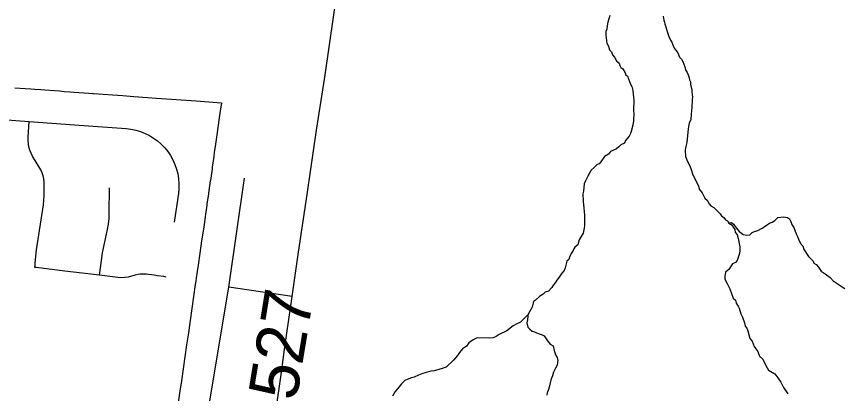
# Model space of a CAD drawing. Extents: x 0 to 39.3, y -3.9 to 22.
# Drawn here: x 5.137 to 6.099, y 18.028 to 18.467 of the extents above; entities that cross this region are included whole.
import ezdxf

# ---------------------------------------------------------------- set-up
doc = ezdxf.new("R2010")
doc.units = 0
for name, color, linetype in [('GM_X_Corporation', 7, 'Continuous'), ('GM_X_Minor_River', 7, 'Continuous'), ('GM_X_State_Route', 7, 'Continuous'), ('GM_X_Township_Road', 7, 'Continuous'), ('GM_X_Township_Road_Text', 7, 'Continuous')]:
    doc.layers.add(name, color=color, linetype=linetype)

msp = doc.modelspace()

# ---------------------------------------------------------------- linework, layer by layer
at = {"layer": 'GM_X_Corporation'}
msp.add_lwpolyline([(5.13496, 18.38436), (5.14692, 18.38347), (5.15336, 18.38299), (5.15826, 18.38263), (5.16517, 18.38212), (5.16959, 18.3818), (5.18092, 18.38096), (5.18693, 18.38052), (5.19225, 18.38012), (5.19923, 18.37961), (5.20359, 18.37928), (5.21492, 18.37846), (5.22098, 18.37801), (5.22526, 18.3777), (5.22625, 18.37763), (5.23759, 18.3768), (5.24892, 18.37597), (5.26025, 18.37515), (5.27336, 18.37419), (5.28901, 18.37305), (5.2995, 18.37228), (5.34556, 18.36892), (5.37507, 18.36676), (5.37501, 18.36637), (5.37372, 18.35735), (5.3722, 18.34667), (5.37012, 18.33214), (5.36817, 18.31847), (5.36678, 18.30877), (5.36615, 18.30432), (5.36439, 18.29203), (5.36411, 18.29009), (5.36214, 18.2763), (5.36211, 18.27607), (5.36006, 18.26176), (5.35996, 18.261), (5.35819, 18.24861), (5.35805, 18.24766), (5.35651, 18.23689), (5.35613, 18.23425), (5.35604, 18.23361), (5.35484, 18.22518), (5.35404, 18.21986), (5.35197, 18.20598), (5.3499, 18.1916), (5.34793, 18.17788), (5.3458, 18.1631), (5.34526, 18.15935), (5.34469, 18.15537), (5.34469, 18.15536), (5.34269, 18.14145), (5.34068, 18.12744), (5.33864, 18.11329), (5.33658, 18.09894), (5.33459, 18.08507), (5.33257, 18.07101), (5.33256, 18.071), (5.33057, 18.0571), (5.33057, 18.0571), (5.32853, 18.04296), (5.32648, 18.02866), (5.32442, 18.01434)], dxfattribs=at)
at = {"layer": 'GM_X_Minor_River'}
for points in [[(5.82631, 18.46825), (5.82428, 18.46068), (5.82345, 18.45651), (5.823, 18.45233), (5.82181, 18.44969), (5.82174, 18.44512), (5.82208, 18.44284), (5.82277, 18.43864), (5.82311, 18.43635), (5.82494, 18.43252), (5.82601, 18.42832), (5.82826, 18.42599), (5.82972, 18.42254), (5.83196, 18.41984), (5.83417, 18.41562), (5.83716, 18.4129), (5.83826, 18.41022), (5.83936, 18.40792), (5.84161, 18.40636), (5.8442, 18.40175), (5.84492, 18.39945), (5.84717, 18.39789), (5.84934, 18.39139), (5.85043, 18.38833), (5.85191, 18.38564), (5.85335, 18.38105), (5.85366, 18.37686), (5.85398, 18.37343), (5.85431, 18.37038), (5.85409, 18.35745), (5.85442, 18.3544), (5.85438, 18.35174), (5.85395, 18.34909), (5.8539, 18.34566), (5.85305, 18.34073), (5.85141, 18.33354), (5.85061, 18.33089), (5.84904, 18.32787), (5.84477, 18.323), (5.84357, 18.3196), (5.83936, 18.31777), (5.83666, 18.31516), (5.83434, 18.3133), (5.83012, 18.31109), (5.82744, 18.30999), (5.82511, 18.30699), (5.82013, 18.30442), (5.81584, 18.29803), (5.8139, 18.29578), (5.81161, 18.29506), (5.80812, 18.29132), (5.80465, 18.28833), (5.80308, 18.2857), (5.80073, 18.28156), (5.79836, 18.27589), (5.79678, 18.2725), (5.79587, 18.26376), (5.79506, 18.26074), (5.79502, 18.25845), (5.79534, 18.25464), (5.79567, 18.2516), (5.796, 18.24854), (5.79693, 18.23598), (5.79718, 18.22875), (5.7971, 18.2238), (5.79667, 18.22077), (5.79543, 18.21508), (5.79074, 18.20718), (5.78912, 18.2015), (5.78566, 18.1989), (5.78448, 18.19664), (5.78329, 18.194), (5.78135, 18.19137), (5.77976, 18.18721), (5.77895, 18.18456), (5.77663, 18.18232), (5.7746, 18.17475), (5.77341, 18.17173), (5.77069, 18.16835), (5.76758, 18.16384), (5.76486, 18.16047), (5.7629, 18.15708), (5.76096, 18.15483), (5.75901, 18.15182), (5.75514, 18.1477), (5.75132, 18.14625), (5.749, 18.14401), (5.74516, 18.14179), (5.74013, 18.13694), (5.73783, 18.13546), (5.7362, 18.12902), (5.7315, 18.12073), (5.73108, 18.11846), (5.73063, 18.11428), (5.73018, 18.11048), (5.73124, 18.10552), (5.73348, 18.1032)], [(5.88864, 18.46753), (5.88933, 18.46296), (5.89005, 18.46066), (5.89039, 18.45837), (5.89148, 18.45531), (5.89329, 18.44995), (5.89509, 18.44384), (5.89692, 18.43962), (5.8984, 18.43731), (5.89987, 18.43424), (5.90132, 18.43041), (5.90319, 18.4281), (5.90541, 18.42502), (5.90761, 18.42003), (5.90985, 18.41771), (5.91133, 18.41502), (5.9135, 18.40852), (5.91458, 18.40508), (5.91643, 18.402), (5.91753, 18.39932), (5.91861, 18.39587), (5.91895, 18.39359), (5.92005, 18.39129), (5.92039, 18.38862), (5.92108, 18.38442), (5.9218, 18.38213), (5.92176, 18.37985), (5.92208, 18.37604), (5.92242, 18.37375), (5.92199, 18.37071), (5.92183, 18.36121), (5.92094, 18.35361), (5.92045, 18.34715), (5.91886, 18.343), (5.91804, 18.33921), (5.91717, 18.33276), (5.91582, 18.32061), (5.91458, 18.31455), (5.91414, 18.31113), (5.91441, 18.30428), (5.91659, 18.29854), (5.91955, 18.29354), (5.921, 18.28933), (5.92279, 18.28283), (5.92501, 18.27937), (5.92721, 18.27439), (5.92942, 18.27016), (5.93012, 18.26635), (5.93384, 18.2621), (5.93678, 18.25558), (5.94016, 18.25324), (5.94162, 18.24941), (5.94385, 18.24671), (5.94724, 18.24475), (5.94986, 18.24242), (5.95248, 18.23971), (5.95472, 18.23739), (5.9562, 18.23508), (5.9592, 18.23274), (5.96107, 18.23043), (5.96333, 18.22925), (5.9648, 18.22656), (5.96856, 18.22421), (5.97004, 18.22152), (5.9719, 18.21921), (5.97223, 18.21616), (5.97446, 18.21308), (5.97553, 18.20887)], [(5.96456, 18.22699), (5.96785, 18.22726), (5.9701, 18.22532), (5.97383, 18.22069), (5.9768, 18.21684), (5.97906, 18.21528), (5.98131, 18.21333), (5.98586, 18.21287), (5.98929, 18.21319), (5.99199, 18.21581), (5.99467, 18.2169), (5.99849, 18.21798), (6.00348, 18.22093), (6.00579, 18.22241), (6.00963, 18.22501), (6.01194, 18.22649), (6.01501, 18.22796), (6.01808, 18.2298), (6.02156, 18.23317), (6.02842, 18.23419), (6.03297, 18.23335), (6.03522, 18.23179), (6.03632, 18.22948), (6.03852, 18.2245), (6.04037, 18.2218), (6.04182, 18.21722), (6.04327, 18.21339), (6.04476, 18.21108), (6.04584, 18.20802), (6.04804, 18.20303), (6.05102, 18.19956), (6.05174, 18.19688), (6.05729, 18.18804), (6.0629, 18.18261), (6.06362, 18.17993), (6.06625, 18.17837), (6.06886, 18.17528), (6.07221, 18.17066), (6.07672, 18.16753), (6.08273, 18.16324), (6.08608, 18.15938), (6.0906, 18.15664), (6.09662, 18.15273), (6.09962, 18.15077)], [(5.97553, 18.20887), (5.97764, 18.19894), (5.97757, 18.19476), (5.97713, 18.19135), (5.97434, 18.18341), (5.97239, 18.18078), (5.96895, 18.17932), (5.96739, 18.17706), (5.96466, 18.17293), (5.9608, 18.16957), (5.95996, 18.16502), (5.96029, 18.16159), (5.96286, 18.1566), (5.9658, 18.15008), (5.9698, 18.13936), (5.97242, 18.13704), (5.9735, 18.13359), (5.97572, 18.13013), (5.97682, 18.12783), (5.97861, 18.12095), (5.98083, 18.11711), (5.983, 18.1106), (5.98369, 18.10679), (5.98555, 18.10447), (5.98702, 18.1014), (5.98916, 18.09262), (5.99176, 18.08915), (5.99432, 18.08302), (5.99617, 18.08032), (5.9984, 18.07724), (6.00059, 18.07187), (6.00433, 18.06839), (6.00763, 18.0611), (6.01097, 18.05572), (6.01812, 18.05141), (6.02184, 18.04678), (6.02518, 18.04177), (6.02849, 18.03525), (6.03331, 18.02794)], [(5.73133, 18.11986), (5.72259, 18.11138), (5.71838, 18.10955), (5.71416, 18.10734), (5.70684, 18.10139), (5.69802, 18.09698), (5.69418, 18.09476), (5.69074, 18.0933), (5.68655, 18.093), (5.67211, 18.09325), (5.66751, 18.09105), (5.6625, 18.08733), (5.65978, 18.08358), (5.65516, 18.08023), (5.65167, 18.07611), (5.64933, 18.07273), (5.64468, 18.0671), (5.63617, 18.05888), (5.63273, 18.0578), (5.62662, 18.05601), (5.62242, 18.05494), (5.61823, 18.05425), (5.61288, 18.05283), (5.60791, 18.05139), (5.60409, 18.04994), (5.5991, 18.04736), (5.59605, 18.04666), (5.59299, 18.04557), (5.58801, 18.04338), (5.58415, 18.03964), (5.57949, 18.03402), (5.57715, 18.03063), (5.57402, 18.02536)], [(5.73348, 18.1032), (5.7361, 18.10087), (5.73875, 18.10006), (5.74139, 18.09888), (5.74555, 18.09766), (5.74782, 18.09686), (5.75008, 18.09568), (5.75416, 18.08952), (5.75714, 18.08567), (5.76053, 18.08371), (5.76196, 18.07836), (5.76268, 18.07606), (5.76339, 18.07338), (5.76524, 18.07031), (5.76594, 18.06687), (5.76553, 18.0646), (5.7651, 18.06156), (5.76351, 18.05779), (5.76116, 18.05326), (5.75994, 18.0491), (5.75875, 18.04608), (5.75795, 18.04381), (5.75714, 18.04078), (5.75592, 18.03586), (5.75511, 18.03321), (5.75352, 18.02905), (5.7531, 18.0264)]]:
    msp.add_lwpolyline(points, dxfattribs=at)
at = {"layer": 'GM_X_State_Route'}
msp.add_lwpolyline([(5.39661, 17.70778), (5.40454, 17.74242), (5.41021, 17.78467), (5.41899, 17.85362), (5.42754, 17.92239), (5.43621, 17.99379), (5.445, 18.05325), (5.44884, 18.08292), (5.45585, 18.13046), (5.45728, 18.14137), (5.4643, 18.19014), (5.47518, 18.26261), (5.48537, 18.33475), (5.4953, 18.39669), (5.50563, 18.46932), (5.5167, 18.54341), (5.52615, 18.6076), (5.53853, 18.69319), (5.54726, 18.75446), (5.55381, 18.80293), (5.55541, 18.8138)], dxfattribs=at)
at = {"layer": 'GM_X_Township_Road'}
msp.add_line((5.45728, 18.14137), (5.38378, 18.15203), dxfattribs=at)
for points in [[(5.10471, 18.34836), (5.15172, 18.3449), (5.20439, 18.34109), (5.26418, 18.33675), (5.26986, 18.33609), (5.27546, 18.33494), (5.28094, 18.33332), (5.28625, 18.33123), (5.29137, 18.32868), (5.29625, 18.32571), (5.30086, 18.32233), (5.30516, 18.31856), (5.30911, 18.31444), (5.3127, 18.30999), (5.31589, 18.30525), (5.31866, 18.30025), (5.32099, 18.29503), (5.32286, 18.28963), (5.32426, 18.28409), (5.32518, 18.27845), (5.32561, 18.27276), (5.32555, 18.26704), (5.32499, 18.26135), (5.32012, 18.22773)], [(5.31094, 18.164), (5.30796, 18.16443), (5.30091, 18.16544), (5.2968, 18.16604), (5.29357, 18.1665), (5.29023, 18.16698), (5.28795, 18.16721), (5.28601, 18.16738), (5.2832, 18.16734), (5.28217, 18.16732), (5.28074, 18.16715), (5.27835, 18.16686), (5.27461, 18.16599), (5.27061, 18.16498), (5.26669, 18.16397), (5.26267, 18.16338), (5.25862, 18.16322), (5.25457, 18.1635), (5.23348, 18.16608), (5.19313, 18.17096), (5.15981, 18.17499), (5.15828, 18.17522), (5.15847, 18.17782), (5.15865, 18.18028), (5.15925, 18.18842), (5.15959, 18.19211), (5.16008, 18.19579), (5.16807, 18.24804), (5.16874, 18.25338), (5.16909, 18.25874), (5.16915, 18.26412), (5.16895, 18.27476), (5.16865, 18.27839), (5.16789, 18.28195), (5.16667, 18.28538), (5.16503, 18.28863), (5.15551, 18.30483), (5.15374, 18.30822), (5.15233, 18.31176), (5.15127, 18.31543), (5.1506, 18.31919), (5.1503, 18.32299), (5.15039, 18.32681), (5.15172, 18.3449)], [(5.35477, 17.97783), (5.38378, 18.15203), (5.4018, 18.27895)], [(5.23348, 18.16608), (5.23591, 18.18593), (5.23649, 18.18995), (5.23724, 18.19394), (5.24261, 18.21922), (5.24373, 18.22557), (5.24442, 18.23197), (5.24467, 18.23841), (5.24482, 18.26762)]]:
    msp.add_lwpolyline(points, dxfattribs=at)

# ---------------------------------------------------------------- texts
at = {"layer": 'GM_X_Township_Road_Text'}
msp.add_text('T-527', height=0.056818, rotation=80.67597, dxfattribs=at).set_placement((5.45038, 17.94791))

doc.saveas('drawing.dxf')
